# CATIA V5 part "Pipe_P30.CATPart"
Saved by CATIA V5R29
Part number: Pipe_P30X1321L
Bounding box of the stored display mesh (mm): x -14.936 to 14.936, y -15 to 15, z -1321 to 0
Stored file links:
  C:\Users\Administrator\Desktop\프로젝트\Boxfold\Pipe_P30.CATPart
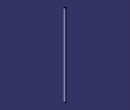
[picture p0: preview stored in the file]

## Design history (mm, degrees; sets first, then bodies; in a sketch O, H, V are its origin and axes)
Body1 (main body)
  DatumSurface1
  Sketch1 on xy-plane, origin (0, 0, 0), H (0, 1, 0), V (1, 0, 0)
    circle A1 centre (0, 0) radius 15
    radius A1 = 15
  Pad1: profile Sketch1, direction (0, 0, -1), length 1321
  DatumCurve1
